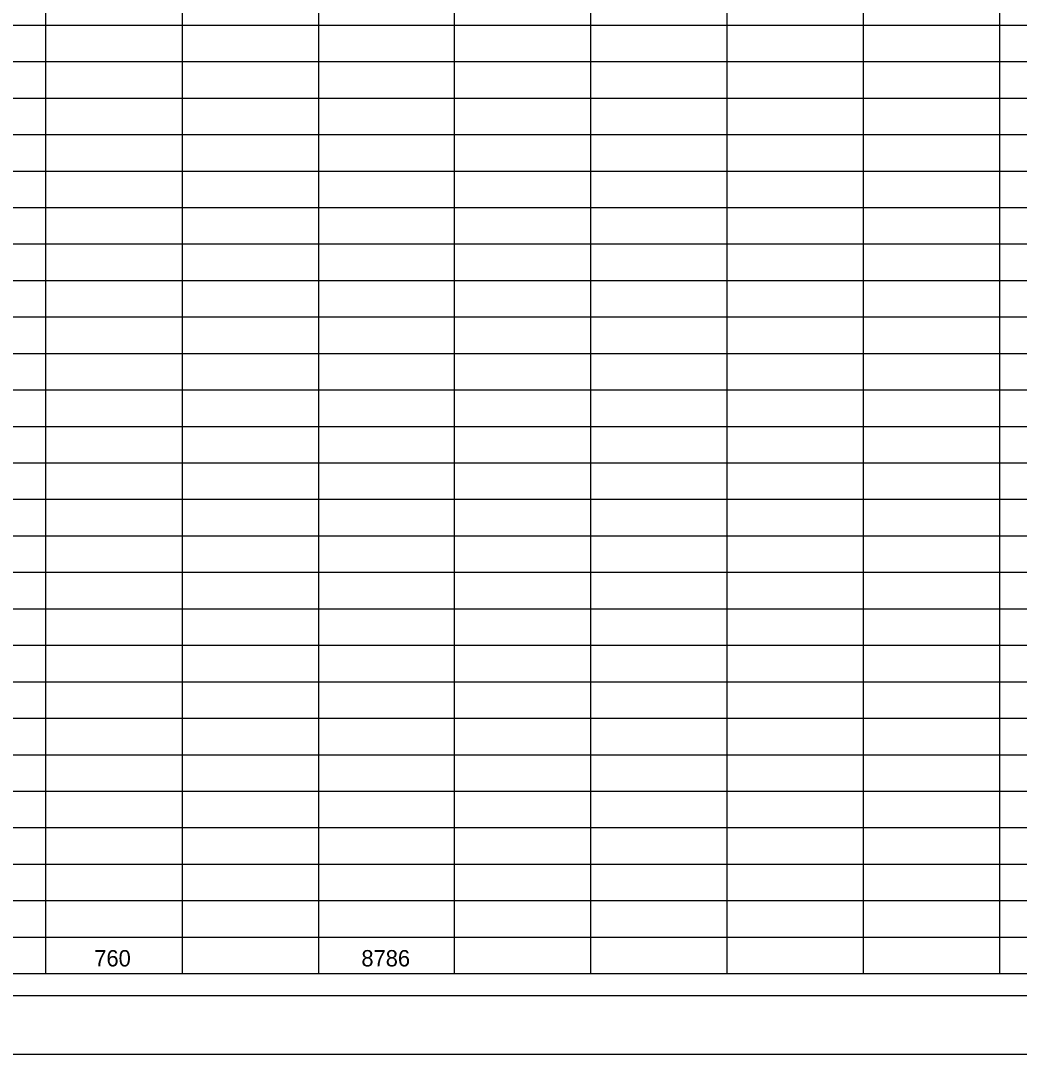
# Model space of a CAD drawing. Extents: x 0 to 34, y 0 to 22.
# Drawn here: x 16.96 to 25.51, y 0 to 8.84 of the extents above; entities that cross this region are included whole.
import ezdxf

# ---------------------------------------------------------------- set-up
doc = ezdxf.new("R2010")
doc.units = 0
for name, color, linetype in [('Default', 7, 'Continuous'), ('SH_Border', 7, 'Continuous'), ('SH_Cut_Line', 7, 'Continuous'), ('SH_Data', 7, 'Continuous')]:
    doc.layers.add(name, color=color, linetype=linetype)

msp = doc.modelspace()

# ---------------------------------------------------------------- linework, layer by layer
at = {"layer": 'Default'}
for p, q in [((31.167, 8.8), (1.5, 8.8)), ((31.167, 8.488), (1.5, 8.488)), ((31.167, 8.176), (1.5, 8.176)), ((31.167, 7.864), (1.5, 7.864)), ((31.167, 7.552), (1.5, 7.552)), ((31.167, 7.24), (1.5, 7.24)), ((31.167, 6.928), (1.5, 6.928)), ((31.167, 6.616), (1.5, 6.616)), ((31.167, 6.304), (1.5, 6.304)), ((31.167, 5.992), (1.5, 5.992)), ((31.167, 5.68), (1.5, 5.68)), ((31.167, 5.368), (1.5, 5.368)), ((31.167, 5.056), (1.5, 5.056)), ((31.167, 4.744), (1.5, 4.744)), ((31.167, 4.432), (1.5, 4.432)), ((31.167, 4.12), (1.5, 4.12)), ((31.167, 3.808), (1.5, 3.808)), ((31.167, 3.496), (1.5, 3.496)), ((31.167, 3.184), (1.5, 3.184)), ((31.167, 2.872), (1.5, 2.872)), ((31.167, 2.56), (1.5, 2.56)), ((31.167, 2.248), (1.5, 2.248)), ((31.167, 1.936), (1.5, 1.936)), ((31.167, 1.624), (1.5, 1.624)), ((31.167, 1.312), (1.5, 1.312))]:
    msp.add_line(p, q, dxfattribs=at)
at = {"layer": 'SH_Border'}
msp.add_lwpolyline([(1.5, 21.5), (33.5, 21.5), (33.5, 0.5), (1.5, 0.5)], close=True, dxfattribs=at)
at = {"layer": 'SH_Cut_Line'}
msp.add_lwpolyline([(0, 0), (34, 0), (34, 22), (0, 22)], close=True, dxfattribs=at)
at = {"layer": 'SH_Data'}
for p, q in [((17.1753, 21.5), (17.1753, 0.688)), ((18.3454, 21.5), (18.3454, 0.688)), ((19.5114, 21.5), (19.5114, 0.688)), ((20.6732, 21.5), (20.6732, 0.688)), ((21.8392, 21.5), (21.8392, 0.688)), ((23.0052, 21.5), (23.0052, 0.688)), ((23.0052, 21.5), (23.0052, 0.688)), ((23.0052, 21.5), (23.0052, 0.688)), ((24.1712, 21.5), (24.1712, 0.688)), ((24.1712, 21.5), (24.1712, 0.688)), ((24.1712, 21.5), (24.1712, 0.688)), ((24.1712, 21.5), (24.1712, 0.688)), ((25.3371, 21.5), (25.3371, 0.688)), ((31.167, 1), (1.5, 1)), ((31.167, 0.688), (16.75, 0.688))]:
    msp.add_line(p, q, dxfattribs=at)

# ---------------------------------------------------------------- texts
for s, p in [('760', (17.5925, 0.7517)), ('8786', (19.8781, 0.7517))]:
    msp.add_text(s, height=0.14, dxfattribs=at).set_placement(p)

doc.saveas('drawing.dxf')
